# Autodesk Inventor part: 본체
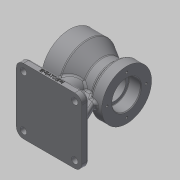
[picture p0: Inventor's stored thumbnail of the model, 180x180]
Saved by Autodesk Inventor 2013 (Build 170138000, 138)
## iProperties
Created: 2019-01
Part Number: 본체
Material: 일반
Document SubType Name: Modeling
Designer: dgall
Density: 1 g/cm^3
Author: dgall
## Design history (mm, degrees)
sketch "스케치1"
  geometry: L1 (46, 46)-(-46, 46); L2 (-46, 46)-(-46, -46); L3 (-46, -46)-(46, -46); L4 (46, -46)-(46, 46); L5 (46, 46)-(-46, -46); L6 (-46, 46)-(46, -46); 1 further point
  constraints: 12 end point, 2 midpoint, 2 parallel, 1 horizontal, 1 perpendicular
  dimensions: "d0" = 92 distance of L1.end L2.end; "d2" = 92 distance of L2.end L3.end
extrude "돌출1" new body sketch "스케치1" distance "d3" = 10; taper "d4" = 0 deg
sketch "스케치2"
  geometry: L1 (46, -46)-(46, 46) reference; L2 (-46, 46)-(-46, -46) reference; L3 (-46, 0)-(-16, 0); L4 (-16, 0)-(36, 0); L5 (-0.801, -5)-(36, -5); L6 (36, -5)-(36, 5); L7 (36, 5)-(-0.801, 5); L8 (-5.291, -5)-(36, 5); L9 (36, -5)-(-5.291, 5); A1 r 16 centre (-16, 0) between (-0.801, 5) and (-0.801, -5); 2 further points
  constraints: 14 end point, 3 midpoint, 3 perpendicular, 2 parallel, 2 point on circle, 1 centre point, 1 coincident, 1 point on line
  dimensions: "d5" = 30 distance of L3.start L3.end; "d7" = 32 diameter of A1; "d8" = 10 distance from line of L1 L4.end; "d9" = 10 distance of L6.end L5.end
extrude "돌출2" join sketch "스케치2" distance "d10" = 70; taper "d11" = 0 deg
sketch "스케치3"
  geometry: L1 (36.801, 0)-(2.798, 72.92); L2 (46.801, -10)-(46.801, 0) reference; L3 (2.798, 72.92)-(46.801, 72.92); L4 (46.801, 72.92)-(36.801, 0); 1 further point
  constraints: 6 end point, 1 perpendicular
  dimensions: "d12" = 25 deg angle of L2 L1
extrude "돌출3" cut sketch "스케치3" distance "d13" = 70; taper "d14" = 0 deg
fillet "모깎기1" dims "d15" = 10
sketch "스케치4"
  geometry: L1 (0, 0)-(0, 80); L2 (-46, 10)-(-46, 0) reference; L3 (-51, 80)-(29, 80); L4 (-51, 80)-(-51, 120); L5 (-51, 120)-(-26, 120); L6 (-26, 120)-(-5.215, 108); L7 (-5.215, 108)-(8.126, 108); L8 (8.126, 108)-(14, 115); L9 (14, 115)-(29, 115); L10 (29, 80)-(29, 115)
  constraints: 18 end point, 4 perpendicular, 2 parallel, 1 vertical
  dimensions: "d16" = 80 distance of L1.start L1.end; "d19" = 80 distance of L3.start L3.end; "d20" = 5 distance from line of L2 L3.start; "d21" = 40 distance of L3.start L4.end; "d22" = 25 distance of L4.end L5.end; "d23" = 15 distance of L8.end L9.end; "d24" = 30 deg angle of L7 L6; "d25" = 50 deg angle of L7 L8; "d27" = 35 distance of L3.end L9.end; "d28" = 28 distance between parallel lines of L3 L7
revolve "회전1" sketch "스케치4" stored, may be unused: angle "d26" = 90 deg
sketch "스케치5"
  geometry: L1 (0, 0)-(0, 80); L2 (-51, 80)-(29, 80); L3 (-46, 10)-(-46, 0) reference; L4 (-51, 80)-(-51, 106); L5 (-51, 106)-(-31, 106); L6 (-31, 106)-(-31, 80); L7 (-31, 96)-(12, 96); L8 (12, 96)-(12, 80); L9 (12, 80)-(12, 100); L10 (12, 100)-(29, 100); L11 (29, 100)-(29, 80)
  constraints: 20 end point, 6 perpendicular, 3 point on line, 2 parallel, 1 collinear, 1 vertical
  dimensions: "d29" = 80 distance of L1.start L1.end; "d30" = 5 distance from line of L3 L2.start; "d31" = 80 distance of L2.start L2.end; "d32" = 20 distance of L4.end L5.end; "d33" = 26 distance of L2.start L4.end; "d34" = 16 distance of L7.end L8.end; "d35" = 17 distance of L9.end L10.end; "d36" = 20 distance of L10.end L2.end
revolve "회전2" sketch "스케치5" stored, may be unused: angle "d37" = 90 deg
sketch "스케치6"
  geometry: C1 r 4.5 at (36, 36); C2 r 4.5 at (36, -36); C3 r 4.5 at (-36, 36); C4 r 4.5 at (-36, -36); A1 r 10 centre (-36, 36) between (-36, 46) and (-46, 36) reference; A2 r 10 centre (-36, -36) between (-46, -36) and (-36, -46) reference; A3 r 10 centre (36, -36) between (36, -46) and (46, -36) reference; A4 r 10 centre (36, 36) between (46, 36) and (36, 46) reference; 1 further point
  constraints: 4 centre point, 4 coincident
  dimensions: "d38" = 9 diameter of C1; "d39" = 9 diameter of C2; "d40" = 9 diameter of C3; "d41" = 9 diameter of C4
extrude "돌출4" cut sketch "스케치6" distance "d42" = 70; taper "d43" = 0 deg
fillet "모깎기2" dims "d44" = 3
fillet "모깎기3" dims "d45" = 3
fillet "모깎기4" dims "d46" = 3
fillet "모깎기5" dims "d47" = 3
fillet "모깎기6" dims "d48" = 1
fillet "모깎기7" dims "d49" = 0.6
chamfer "모따기1" distance "d50" = 1; stored, may be unused: second distance "d51" = 2, angle "d52" = 45 deg
chamfer "모따기2" distance "d53" = 1; stored, may be unused: second distance "d54" = 2, angle "d55" = 45 deg
sketch "스케치7" dims "d56" = 66
  geometry: C1 r 27 at (0, 0) reference; 3 further points
  constraints: 1 coincident, 1 vertical alignment, 2 other
hole "구멍1" sketch "스케치7" at (0, 33) diameter "d58" = 3.242; stored, may be unused: countersink angle "d62" = 90 deg, drill point angle "d64" = 118 deg; dims "d59" = 9, "d60" = 4, "d61" = 2, "d63" = 11
sketch "스케치8" dims "d68" = 55
  geometry: C1 r 21 at (0, 0) reference; 3 further points
  constraints: 1 coincident, 1 vertical alignment, 2 other
hole "구멍2" sketch "스케치8" at (0, 27.5) diameter "d70" = 3.242; stored, may be unused: countersink angle "d74" = 90 deg, drill point angle "d76" = 118 deg; dims "d71" = 9, "d72" = 4, "d73" = 2, "d75" = 11
sketch "스케치9"
  geometry: L1 (0, 0)-(72, 0) reference; L2 (-10, 7)-(-10, 0) reference; 2 further points
  constraints: 1 other
  dimensions: "d80" = 4 distance from line of L1 point (36, 4); "d81" = 46 distance from line of L2 point (36, 4)
feature "엠보싱1" sketch "스케치9" dims "d0" = 92, "d2" = 92, "d82" = 0.5, "d83" = 0
node "솔리드1"
pattern_circular "원형 패턴1" dims angle "d66" = 360 deg
pattern_circular "원형 패턴2" dims angle "d78" = 360 deg
